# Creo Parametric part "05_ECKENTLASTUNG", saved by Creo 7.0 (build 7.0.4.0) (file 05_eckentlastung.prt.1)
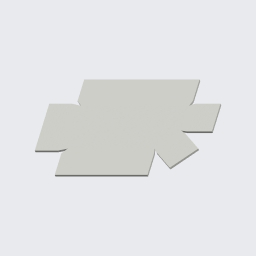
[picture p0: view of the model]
Units: millimeter Kilogram Sec (mmKs); MM, KILOGRAM, SECS
Materials in the file: S235JRG2

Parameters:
  PTC_MATERIAL_NAME = "S235JRG2"
  BENENNUNG = "XXX"
  DATUM = "XX.XX.XX"
  ERSTELLER = "ARINDA"
  TEILETYP = "Fertigungsteil"
  SMT_DFLT_BEND_REL_LENGTH_TYPE = "Through All"
  SELECT_EN_NAME = "S235JRG2"
  SELECT_DIN_NAME = "RSt37-2"
  SELECT_DIN_NUMBER = "1.0038"
  SELECT_ASTM_NAME = "A 283 M Grade 2"
  MATERIAL_GROUP = "ME_ST_Baustahl"
  STANDARD_EN_DELIVERYSPEC = "DIN EN 10025"
  STANDARD_DIN_DELIVERYSPEC = "DIN 17100"

Other parameters: MASSE, SMT_THICKNESS, SMT_PART_BEND_ALLOWANCE_FACTOR, SMT_DFLT_BEND_RADIUS, SMT_DFLT_BEND_ANGLE, SMT_DFLT_CRNR_REL_WIDTH, SMT_DFLT_CRNR_REL_DEPTH, SMT_DFLT_BEND_REL_WIDTH, SMT_DFLT_BEND_REL_DEPTH, SMT_DFLT_BEND_REL_LENGTH, SMT_DFLT_BEND_REL_ANGLE, SMT_GAP, SMT_DFLT_EDGE_TREA_WIDTH, SMT_DFLT_MITER_CUT_WIDTH, SMT_DFLT_MITER_CUT_OFFSET, D10, D18, SMT_FLAT_PATTERN_LENGTH

Created from: ARINDA-STARTTEIL.PRT

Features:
  1. coordinate system
  2. datum plane "T_RECHTS_Y-Z"
  3. datum plane "T_OBEN_X-Z"
  4. datum plane "T_VORNE_X-Y"
  5. datum axis "T_X-ACHSE"
  6. datum axis "A_1"
  7. datum axis "A_2"
  8. extrusion "Profil 1"
  9. feature "Konvertieren(Erste Lasche)"
  10. feature "Konvertierung 1"
  11. feature "Endabwicklung 1"

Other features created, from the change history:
  chamfer "Fase 1"

Other named items: T_BASIC, T_Y-ACHSE, T_Z-ACHSE, FLAT_PATTERN_WIDTH, FLAT_PATTERN_LENGTH

Layers: 00_STD-ACHSEN, 00_STD-EBENEN, 00_STD-KOORDSYS, 01_ACHSEN, SAMMELFLÄCHEN, VOLUMENGEOMETRIE

Notes: 90.00°

Surfaces: 44 plane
